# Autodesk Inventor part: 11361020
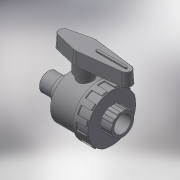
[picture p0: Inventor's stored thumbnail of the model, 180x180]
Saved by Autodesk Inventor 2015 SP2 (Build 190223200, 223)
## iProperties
Created: 2017-11
Part Number: 11361020
Material: Generic
Description: PLASSON ONE NUT VALVE MALE-FEMALE ADAPTOR 2" PVC
Document SubType Name: Modeling
Designer: KIM
Density: 1 g/cm^3
Appearance: Default
Author: KIM
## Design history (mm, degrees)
derived "113610.ipt"
feature "Solid1::113610.ipt"
tag "TaggingFeature1"
body "Solid1"
other parameters: "d0" = 159, "d2" = 118, "d4" = 45.3248, "d8" = 106.2, "d13" = 1.69968, "d25" = 1.13312, "d26" = 1.69968, "d29" = 19.5, "d30" = 0, "d35" = 1.69968, "d39" = 59, "d45" = 360 deg, "d47" = 1.13312, "d50" = 64.9, "d51" = 35.4, "d53" = 0, "d58" = 0, "d59" = 1.69968, "d63" = 47.2, "d64" = 106, "d66" = 129, "d68" = 23.6, "d69" = 38.7, "d70" = 26.5, "d71" = 3 deg, "d73" = 2.36, "d74" = 51.6, "d75" = 3.18, "d76" = 0, "d77" = 1.13312, "d78" = 56.656, "d79" = 26, "d80" = 118, "d81" = 27.3, "d82" = 113.28, "d83" = 20.8, "d84" = 79.3184, "d85" = 41.7298, "d87" = 120 deg, "d90" = 360 deg, "d92" = 17.7, "d95" = 8.85, "d96" = 59.614, "d97" = 31.2, "d98" = 26, "d99" = 15 deg, "d100" = 71.5368, "d101" = 11.3312, "d102" = 5.6656, "G_" = 56.656, "l_" = 26, "H_" = 159, "K_" = 118, "F_" = 106, "J_" = 129, "R_" = 59.614, "d67" = 47.2, "d72" = 11.8
